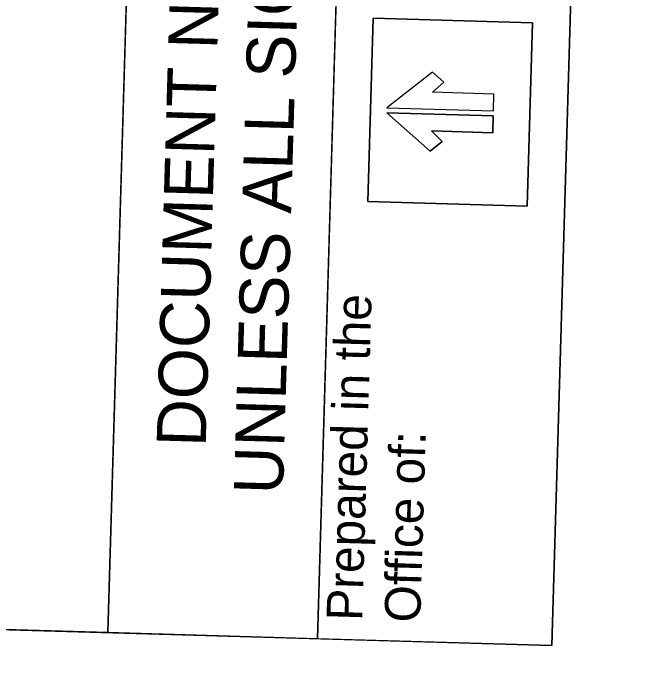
# Model space of a CAD drawing. Extents: x 2096999 to 2102576, y 682920 to 687015.
# Drawn here: x 2097239.6 to 2097306.6, y 686627 to 686696.1 of the extents above; entities that cross this region are included whole.
import ezdxf

# ---------------------------------------------------------------- set-up
doc = ezdxf.new("R2010")
doc.units = 0
for name, color, linetype in [('Old_Level_2', 7, 'Continuous'), ('Scratch_Level_2', 7, 'Continuous'), ('Sheet Block Title CELL', 7, 'Continuous'), ('Sheet Sticker Exception Certification CELL', 7, 'Continuous')]:
    doc.layers.add(name, color=color, linetype=linetype)

msp = doc.modelspace()

# ---------------------------------------------------------------- linework, layer by layer
at = {"layer": 'Old_Level_2'}
msp.add_lwpolyline([(2097138.11, 686634.558), (2097143.573, 686821.425), (2097254.903, 686818.17), (2097249.44, 686631.303)], close=True, dxfattribs=at)
msp.add_lwpolyline([(2097138.11, 686634.558), (2097143.573, 686821.425), (2097254.903, 686818.17), (2097249.44, 686631.303)], close=True, dxfattribs=at)
at = {"layer": 'Scratch_Level_2'}
msp.add_lwpolyline([(2097234.321, 685317.776), (2097026.761, 685323.81), (2097058.723, 686423.238), (2097059.306, 686437.009), (2097065.144, 686636.691), (2097214.22, 686632.333), (2097231.796, 686631.819), (2097295.872, 686629.946), (2097298.79, 686729.775), (2098044.583, 686708.094), (2098037.226, 686456.473), (2098110.07, 686454.344), (2098090.846, 685704.417)], close=True, dxfattribs=at)
at = {"layer": 'Sheet Block Title CELL'}
for points in [[(2097271.371, 686630.662), (2097276.829, 686817.346), (2097301.33, 686816.629), (2097295.872, 686629.946)], [(2097276.636, 686676.368), (2097277.197, 686695.551), (2097293.847, 686695.064), (2097293.286, 686675.881)], [(2097278.628, 686686.19), (2097289.76, 686685.864), (2097289.812, 686687.618), (2097283.39, 686687.806), (2097284.572, 686688.858), (2097283.382, 686689.915)]]:
    msp.add_lwpolyline(points, close=True, dxfattribs=at)
for points in [[(2097277.197, 686695.551), (2097276.636, 686676.368), (2097293.286, 686675.881), (2097293.847, 686695.064), (2097277.197, 686695.551)], [(2097278.628, 686686.19), (2097289.76, 686685.864), (2097289.812, 686687.618), (2097283.39, 686687.806), (2097284.572, 686688.858), (2097283.382, 686689.915), (2097278.628, 686686.19)], [(2097278.612, 686685.65), (2097289.745, 686685.325), (2097289.693, 686683.571), (2097283.272, 686683.759), (2097284.39, 686682.639), (2097283.14, 686681.653), (2097278.612, 686685.65)], [(2097283.14, 686681.653), (2097284.39, 686682.639), (2097283.272, 686683.759), (2097289.693, 686683.571), (2097289.745, 686685.325), (2097278.612, 686685.65), (2097283.14, 686681.653)]]:
    msp.add_lwpolyline(points, dxfattribs=at)
at = {"layer": 'Sheet Sticker Exception Certification CELL'}
for p, q in [((2097249.44, 686631.303), (2097254.898, 686817.987)), ((2097249.44, 686631.303), (2097254.898, 686817.987)), ((2097276.829, 686817.346), (2097271.371, 686630.662)), ((2097276.829, 686817.346), (2097271.371, 686630.662)), ((2097271.371, 686630.662), (2097249.44, 686631.303)), ((2097271.371, 686630.662), (2097249.44, 686631.303))]:
    msp.add_line(p, q, dxfattribs=at)

# ---------------------------------------------------------------- texts
at = {"layer": 'Sheet Block Title CELL'}
for s, height, p in [('Prepared in the ', 3.73527, (2097276.033, 686632.508)), ('Office of:', 3.7353, (2097282.1, 686632.331))]:
    msp.add_text(s, height=height, rotation=88.3254, dxfattribs=at).set_placement(p)
at = {"layer": 'Sheet Sticker Exception Certification CELL'}
for s, p in [('UNLESS ALL SIGNATURES COMPLETED', (2097267.744, 686645.713)), ('UNLESS ALL SIGNATURES COMPLETED', (2097267.744, 686645.713)), ('DOCUMENT NOT CONSIDERED FINAL', (2097259.67, 686650.685)), ('DOCUMENT NOT CONSIDERED FINAL', (2097259.67, 686650.685))]:
    msp.add_text(s, height=5.13504, rotation=88.3254, dxfattribs=at).set_placement(p)

doc.saveas('drawing.dxf')
